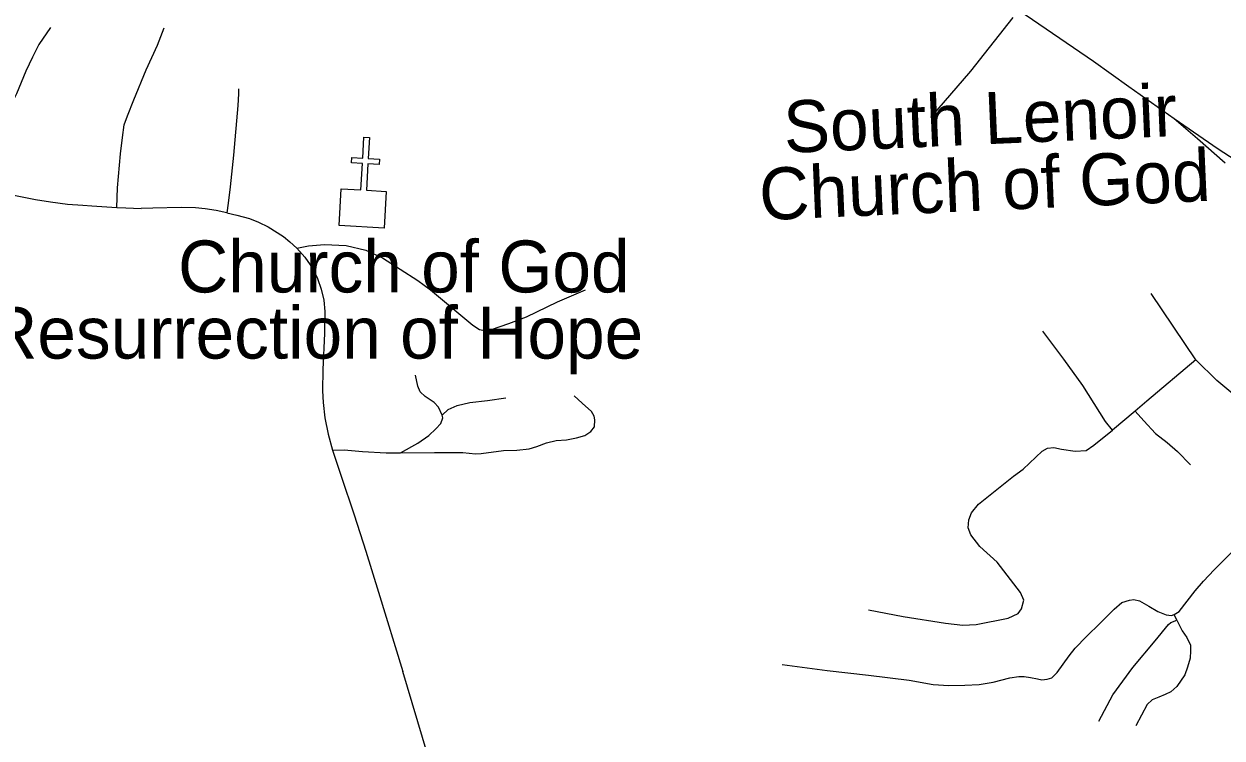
# Model space of a CAD drawing. Extents: x 1159738 to 1321356, y 736314 to 882035.
# Drawn here: x 1249255 to 1252716, y 783806 to 785868 of the extents above; entities that cross this region are included whole.
import ezdxf

# ---------------------------------------------------------------- set-up
doc = ezdxf.new("R2010")
doc.units = 0
for name, color, linetype in [('Exist Cultural Church CELL', 7, 'Continuous'), ('Exist Cultural Church Label', 7, 'Continuous'), ('Exist Railroad Mainline', 7, 'Continuous'), ('Exist Railroad Siding', 7, 'Continuous'), ('Exist Road Non-System Type 51', 7, 'Continuous')]:
    doc.layers.add(name, color=color, linetype=linetype)

msp = doc.modelspace()

# ---------------------------------------------------------------- linework, layer by layer
at = {"layer": 'Exist Cultural Church CELL'}
msp.add_lwpolyline([(1250171.6, 785391.8), (1250228.4, 785388.5), (1250232.9, 785464.6), (1250200.9, 785466.4), (1250201.9, 785482.4), (1250233.8, 785480.5), (1250237.3, 785540.5), (1250253.3, 785539.6), (1250249.8, 785479.6), (1250281.8, 785477.7), (1250280.8, 785461.7), (1250248.9, 785463.6), (1250244.4, 785387.6), (1250301.9, 785384.1), (1250295.7, 785277.8), (1250165.3, 785285.5)], close=True, dxfattribs=at)
at = {"layer": 'Exist Railroad Mainline'}
msp.add_lwpolyline([(1250799.1, 786830.3), (1250879.9, 786775), (1251079.8, 786635.3), (1251208.2, 786547.2), (1251283.7, 786504.5), (1251408.2, 786407.6), (1251467.4, 786368), (1251585.3, 786285.7), (1251695.1, 786208.8), (1251952.1, 786032.7), (1252129.7, 785907.4), (1252344.8, 785760.8), (1252447.2, 785687.6), (1252578.5, 785594.4), (1252705.2, 785507.3), (1252754.7, 785475.1), (1252783.4, 785450.9), (1252891.1, 785378.3), (1253095.8, 785238), (1253246.4, 785134.6), (1253443, 784998.9), (1253517.1, 784947.8), (1253629.3, 784860.3), (1253682.8, 784816)], dxfattribs=at)
at = {"layer": 'Exist Railroad Siding'}
msp.add_lwpolyline([(1252578.5, 785594.4), (1252645.2, 785536.9), (1252725.2, 785466.6)], dxfattribs=at)
at = {"layer": 'Exist Road Non-System Type 51'}
msp.add_line((1252641, 784898), (1252512, 785089.5), dxfattribs=at)
for points in [[(1251874.7, 785597.3), (1251990.5, 785731.6), (1252112.9, 785886.1)], [(1249332, 785858.1), (1249297.7, 785808.5), (1249279.4, 785772.3), (1249260.4, 785731.9), (1249233.4, 785666.3), (1249220, 785639), (1249198, 785602.8)], [(1249523, 785337.9), (1249525.3, 785394.4), (1249533.8, 785493.1), (1249539.3, 785540), (1249544.8, 785576.7), (1249554.6, 785602.5), (1249572.4, 785648.4), (1249608.5, 785735.1), (1249640.9, 785806.8), (1249660.5, 785857.1)], [(1249874.4, 785680.8), (1249874.6, 785666.3), (1249872.8, 785632), (1249859.9, 785489.1), (1249850.7, 785397.7), (1249845.2, 785349.9), (1249840.9, 785322.5)], [(1249084.7, 785415.8), (1249144.2, 785394.8), (1249172.4, 785386.8), (1249206.1, 785377), (1249235.5, 785371.5), (1249288.5, 785361.2), (1249332, 785354.5), (1249380.9, 785347.7), (1249425, 785344.1), (1249451.4, 785342.8), (1249523, 785337.9)], [(1249523, 785337.9), (1249549.1, 785336.8), (1249593.8, 785335)], [(1249840.9, 785322.5), (1249810.2, 785328.7), (1249779, 785334.2), (1249750.8, 785336.6), (1249709.2, 785337.9), (1249627.8, 785336), (1249593.8, 785335)], [(1249840.9, 785322.5), (1249869.8, 785316), (1249906.5, 785305.6), (1249932.2, 785295.8), (1249961, 785282.3), (1250004.4, 785254), (1250023.3, 785239), (1250043, 785220)], [(1250043, 785220), (1250076.9, 785226.9), (1250123.4, 785230.8), (1250185.6, 785227.6), (1250242.4, 785215), (1250290.5, 785192.1), (1250392.9, 785126.7), (1250430, 785099.9), (1250552, 784998.5), (1250570.7, 784985.1), (1250585.7, 784982.7), (1250605.4, 784985.8), (1250655.8, 785003.2), (1250707.1, 785022.1), (1250796.1, 785065.5), (1250877.3, 785100.2)], [(1250043, 785220), (1250066.6, 785194.7), (1250088.7, 785162.4), (1250102.9, 785133.2), (1250113.9, 785102.4), (1250121, 785070.1), (1250124.1, 785037.7), (1250123.4, 784973.9), (1250118.6, 784870.2), (1250117.8, 784808.7), (1250119.4, 784774.8), (1250124.1, 784730.6), (1250133.6, 784683.3), (1250146.3, 784637.3)], [(1252399.6, 784694.8), (1252379.7, 784720), (1252314, 784824), (1252258.8, 784900.3), (1252198.3, 784980.7)], [(1252641, 784898), (1252498.7, 784778.1), (1252465.7, 784749.4), (1252399.6, 784694.8)], [(1253075.5, 784567.6), (1253063.8, 784565.3), (1253046.9, 784567.6), (1253025.2, 784573.1), (1252992.5, 784590.6), (1252970, 784607.3), (1252800.2, 784755.2), (1252701.6, 784838.5), (1252641, 784898)], [(1250463.5, 784738), (1250452.5, 784760.9), (1250439.9, 784774.3), (1250413.9, 784792.4), (1250399.7, 784805.8), (1250393.4, 784821.6), (1250386.3, 784853.2)], [(1250343, 784629.2), (1250440.7, 784630), (1250522.7, 784630), (1250559.7, 784626.8), (1250576.2, 784627.6), (1250640.1, 784636.3), (1250678.7, 784637.1), (1250714.2, 784641), (1250737, 784647.3), (1250764.6, 784658.3), (1250793, 784665.4), (1250822.9, 784667), (1250851.3, 784672.5), (1250875, 784679.6), (1250893.1, 784690.7), (1250903.3, 784704.1), (1250904.1, 784724.6), (1250902.5, 784735.6), (1250894.7, 784748.3), (1250867.9, 784772.7), (1250844.2, 784794)], [(1250463.5, 784738), (1250480.1, 784754.6), (1250506.1, 784765.6), (1250543.1, 784774.3), (1250594.4, 784780.6), (1250647.2, 784787.7)], [(1250343, 784629.2), (1250393.4, 784657.6), (1250424.9, 784679.6), (1250445.4, 784698.6), (1250459.6, 784714.3), (1250465.1, 784730.1), (1250463.5, 784738)], [(1252465.7, 784749.4), (1252490.1, 784722), (1252524.5, 784685.5), (1252557.7, 784659.4), (1252587.5, 784633.3), (1252625.6, 784594.7)], [(1251694.8, 784175.6), (1251795, 784156.6), (1251917.1, 784137), (1251967.9, 784132.1), (1252006.3, 784134), (1252098.6, 784152.3), (1252127, 784165.1), (1252137.4, 784179.1), (1252143.5, 784203.6), (1252133.7, 784226.2), (1252067.1, 784313.6), (1252016.5, 784359.1), (1251990.8, 784392.7), (1251982.9, 784412.9), (1251984.7, 784435.5), (1251992.7, 784455.7), (1252012.8, 784481.4), (1252114.2, 784562.1), (1252141.6, 784582.6), (1252196.6, 784634.6), (1252211.9, 784643.1), (1252230.2, 784644.3), (1252252.8, 784639.5), (1252291.9, 784634), (1252323.7, 784636.4), (1252346.3, 784651.1), (1252399.6, 784694.8)], [(1250146.3, 784637.3), (1250179.9, 784638.1), (1250233.5, 784633.3), (1250301.3, 784629.4), (1250343, 784629.2)], [(1250146.3, 784637.3), (1250171.5, 784562.4), (1250208.6, 784450.4), (1250242.4, 784345), (1250279.4, 784226.7), (1250349.4, 783998.1)], [(1252578.3, 784162.9), (1252592.4, 784171), (1252615.2, 784201.3), (1252638.7, 784231.1), (1252663, 784259.1), (1252693.2, 784291.6), (1252747.8, 784345.5), (1252784.7, 784377.2), (1252818.6, 784401.6), (1252852.5, 784424.4), (1252895.2, 784445.6), (1252935, 784464.8), (1252994.7, 784491.4), (1253023.5, 784505.4), (1253047.8, 784522.4), (1253064, 784537.1), (1253073.6, 784549.7), (1253075.5, 784567.6)], [(1251445.6, 784018.3), (1251575.4, 784000.6), (1251694.9, 783987.3), (1251812.2, 783972.6), (1251882.2, 783960.8), (1251927.2, 783957.8), (1251973.7, 783958.6), (1252015, 783960.8), (1252055.2, 783967.4), (1252103.1, 783980), (1252128.9, 783983.6), (1252144.4, 783983.6), (1252162.9, 783980.7), (1252182.8, 783976.3), (1252196, 783974.1), (1252211.5, 783975.5), (1252224.8, 783980), (1252239.6, 783994.7), (1252274.2, 784043.4), (1252291.9, 784064.8), (1252324.4, 784098.8), (1252363.9, 784137.5), (1252404.4, 784178.1), (1252427.3, 784197.3), (1252448.7, 784203.9), (1252461.2, 784205.4), (1252477.4, 784201.7), (1252504.7, 784187), (1252531.3, 784171.5), (1252554.9, 784161.9), (1252570.4, 784159.6), (1252578.3, 784162.9)], [(1252585.7, 784146), (1252578.3, 784162.9)], [(1252360.1, 783854.4), (1252400.6, 783930.5), (1252458.9, 784009.4), (1252523, 784086.9), (1252561.4, 784133.4), (1252568, 784139.3), (1252585.7, 784146)], [(1252585.7, 784146), (1252601.2, 784115), (1252614.5, 784096.5), (1252624.8, 784073.6), (1252625.5, 784057.4), (1252624.1, 784036.7), (1252616.7, 784010.2), (1252609.3, 783988), (1252585.7, 783954.1), (1252568, 783939.3), (1252552.5, 783931.9), (1252533.4, 783923.8), (1252514.9, 783915.7), (1252500.2, 783902.4), (1252467, 783841.2)], [(1250941.5, 783128.3), (1250868.5, 783146.5), (1250811.8, 783162.3), (1250752.7, 783187.6), (1250718.8, 783206.5), (1250674.6, 783235.7), (1250640.8, 783265.6), (1250598.2, 783312.2), (1250568.2, 783351.6), (1250539.1, 783402.9), (1250514.8, 783455.4), (1250488.8, 783537.5), (1250420.3, 783761.8), (1250349.4, 783998.1)]]:
    msp.add_lwpolyline(points, dxfattribs=at)

# ---------------------------------------------------------------- texts
at = {"layer": 'Exist Cultural Church Label'}
for s, p in [('South Lenoir', (1251452.7, 785495.1)), ('Church of God', (1251382.3, 785300.8))]:
    msp.add_text(s, height=150, rotation=2.4915, dxfattribs=at).set_placement(p)
for s, p in [('Church of God', (1249700.2, 785092.5)), ('Resurrection of Hope', (1249148.8, 784901.5))]:
    msp.add_text(s, height=150, dxfattribs=at).set_placement(p)

doc.saveas('drawing.dxf')
